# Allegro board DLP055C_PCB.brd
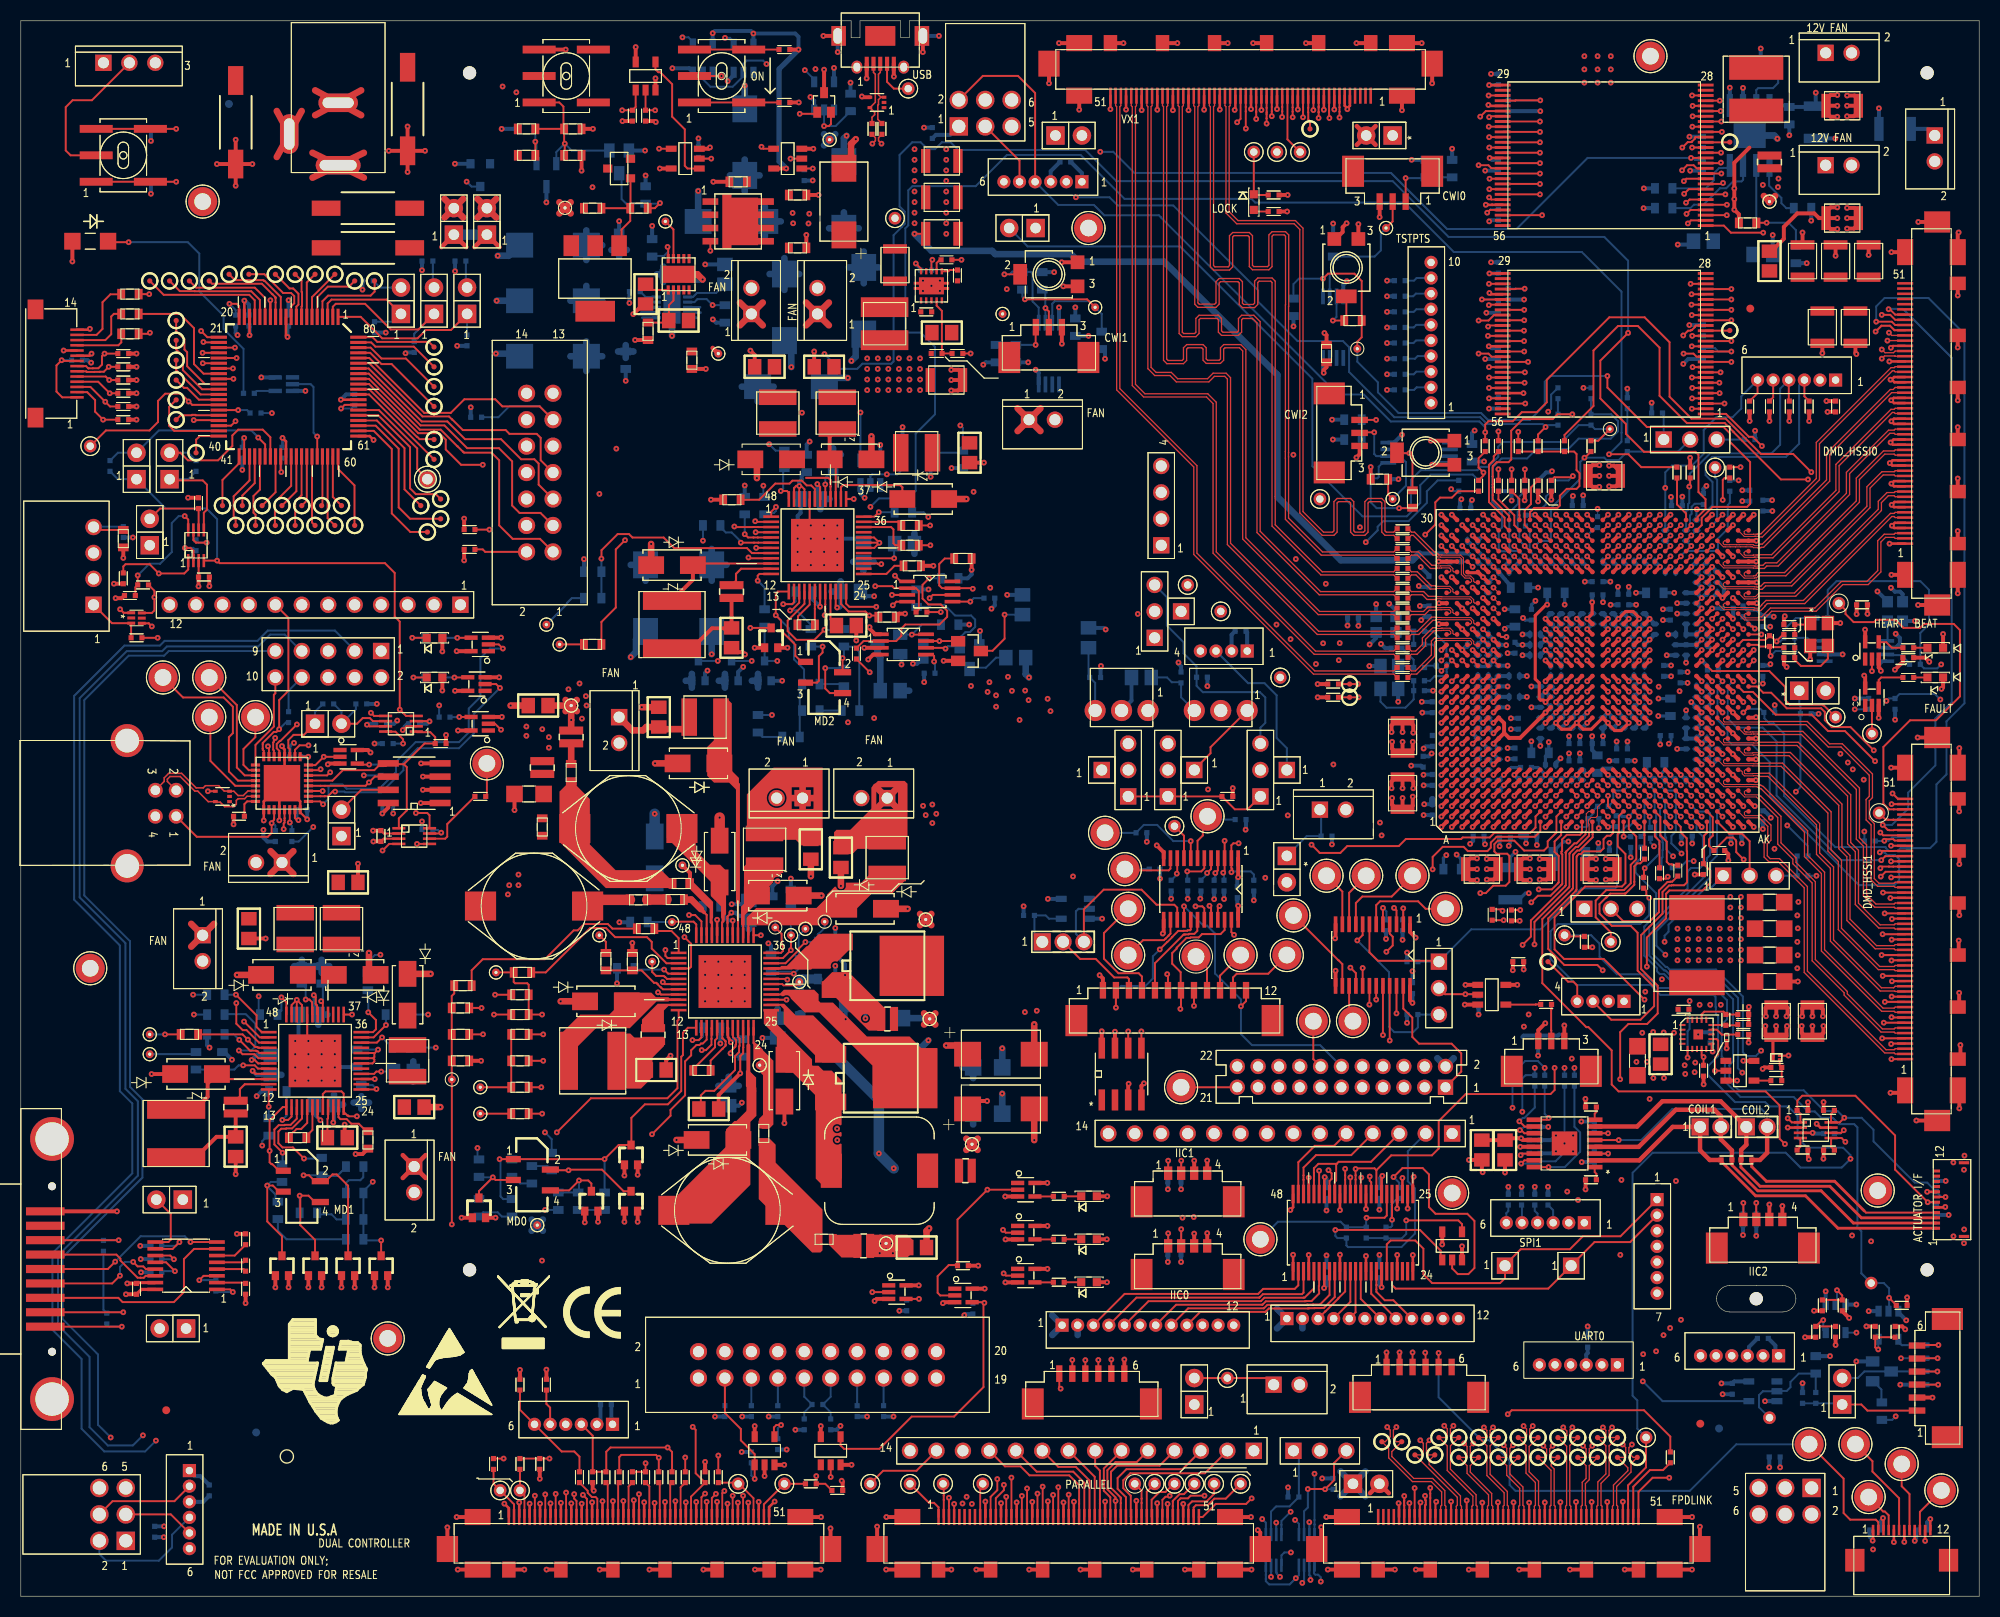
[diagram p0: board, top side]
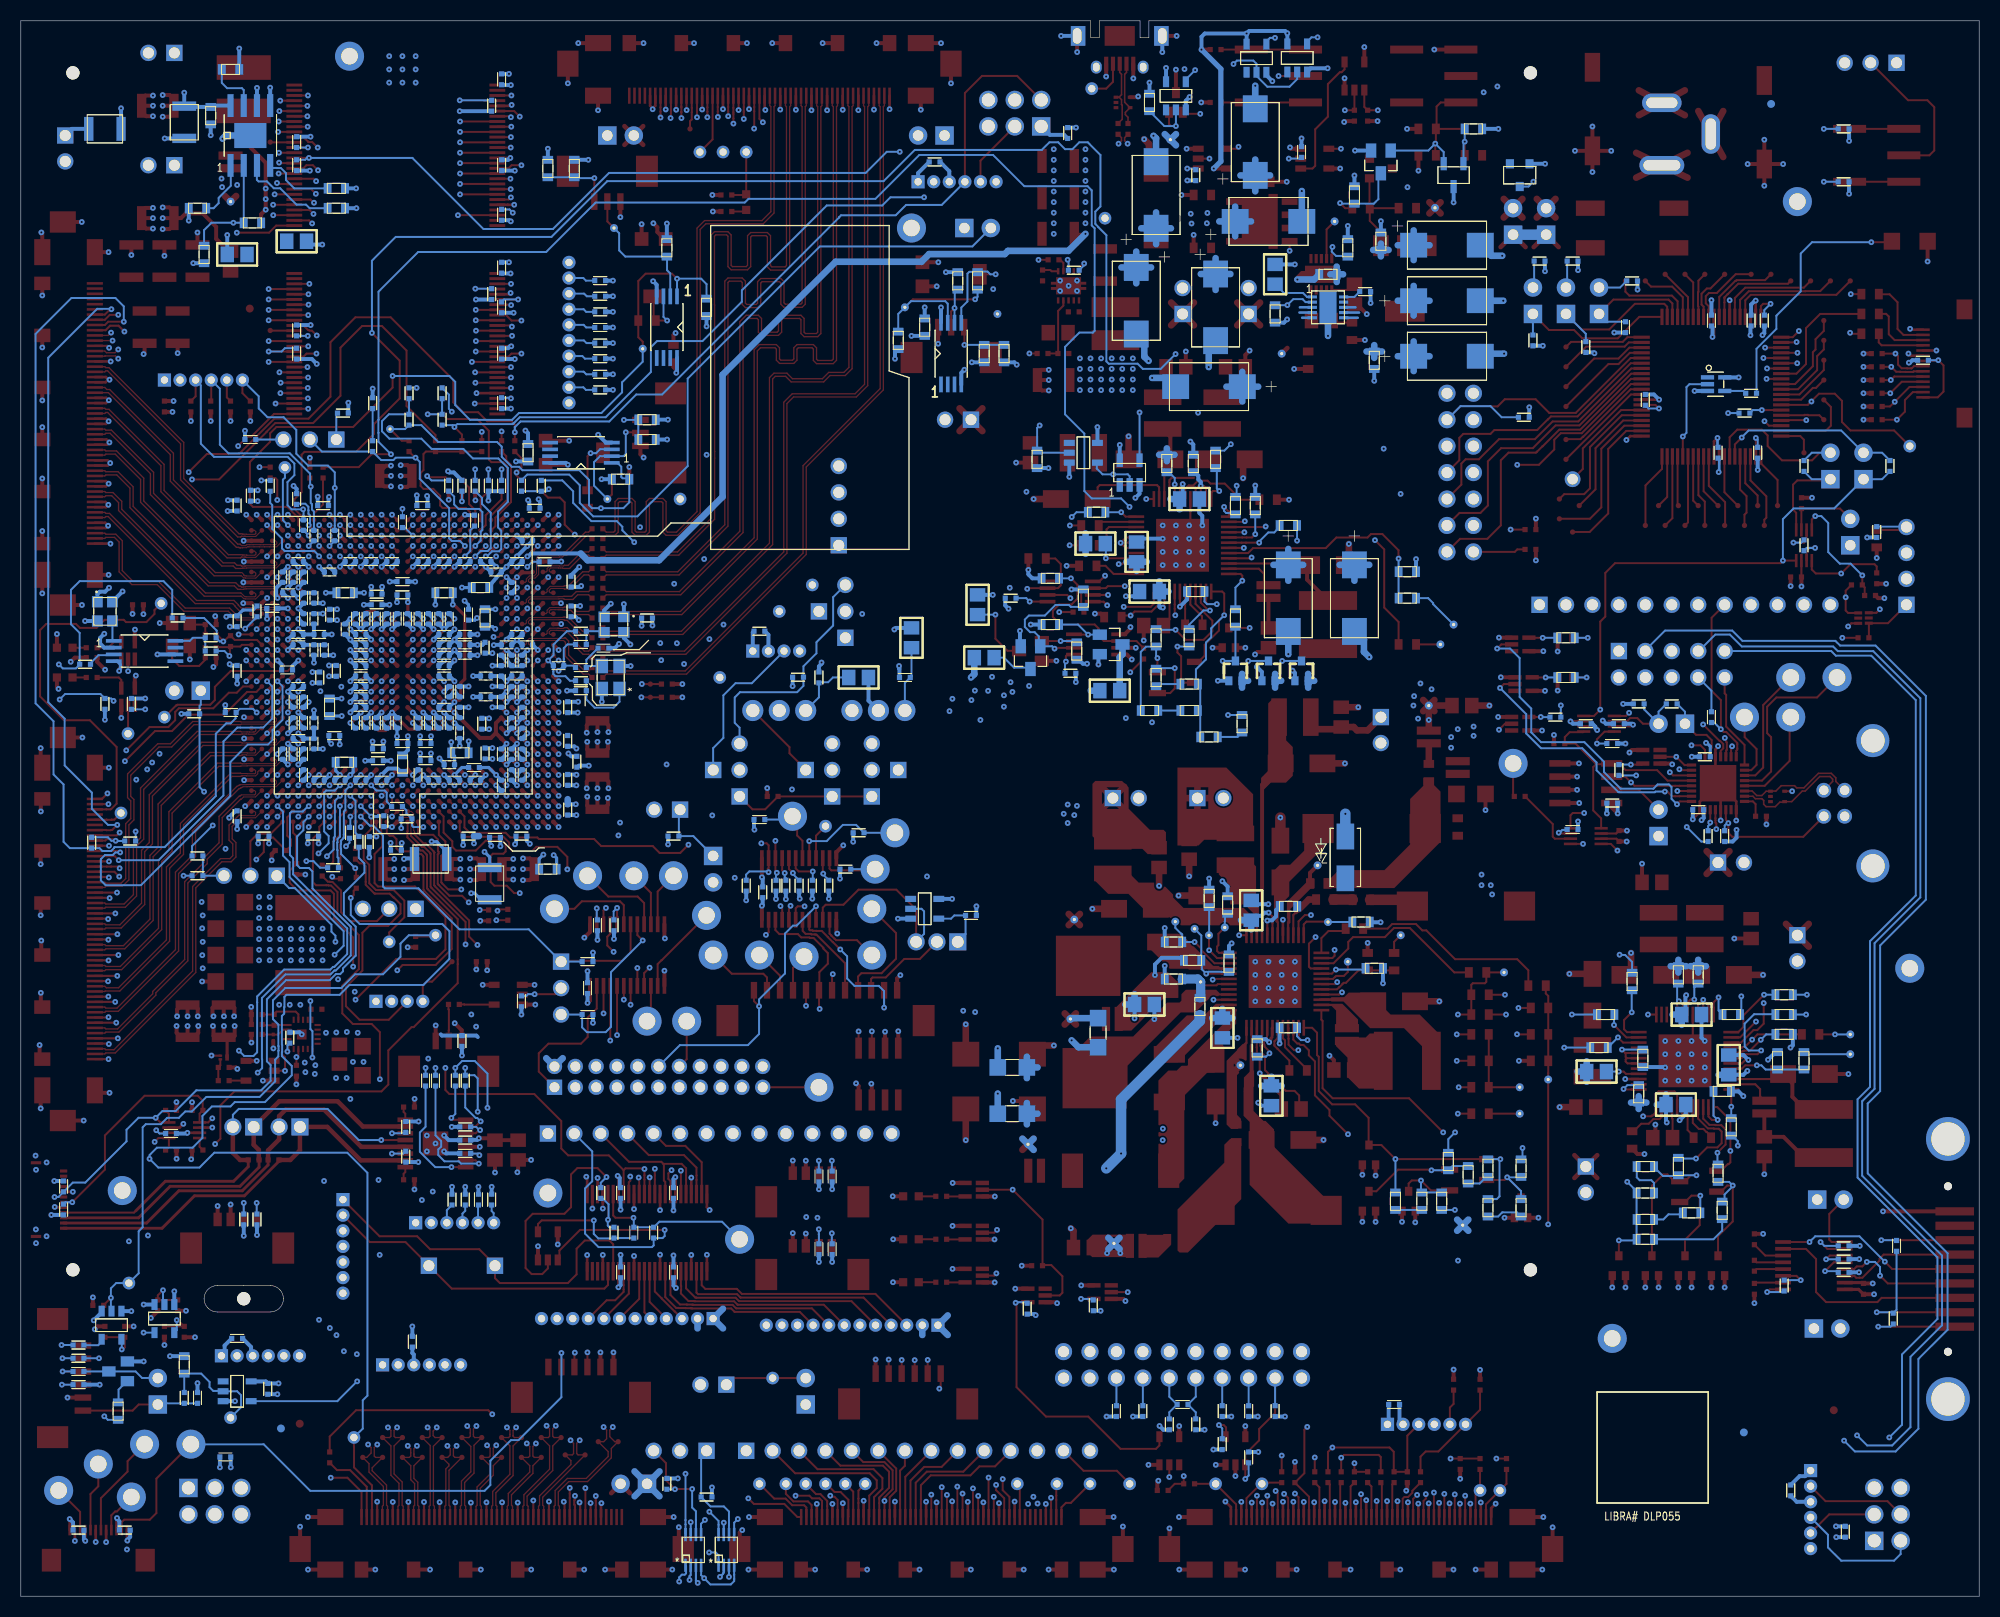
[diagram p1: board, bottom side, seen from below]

Outline 188.1 x 151.35 mm; copper layers: TOP, L2_GND, LY3, LY4_GND, LY5, LY6_GND, LY7_PLANE, LY8_PLANE, LY9_GND, LY10, LY11_GND, LY12, L13_GND, BOTTOM. Coordinates in mm from the lower left corner of the outline.
Outline path: 0,151.35 0,0 188.1,0 188.1,151.35 85.35,151.35 85.35,149.75 84.5,149.75 84.5,151.35 80.6,151.35 80.6,149.75 79.75,149.75 79.75,151.35 0,151.35

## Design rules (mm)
net group DIFFPAIR24: nets DMD_LS0_WDATA_N DMD_LS0_WDATA_P
net group DIFFPAIR37: nets USBDM USBDP
net group GROUP1: nets DMD_LS0_CLK_N DMD_LS0_CLK_P
net group USB_DAT_N: nets USB_DAT_N USB_DAT_N_IN
net group USB_DAT_P: nets USB_DAT_P USB_DAT_P_IN
net group DMD_HSSI0: nets DMD_HSSI0_CLK_N DMD_HSSI0_CLK_P DMD_HSSI0_N_0 DMD_HSSI0_N_1 DMD_HSSI0_N_2 DMD_HSSI0_N_3 DMD_HSSI0_N_4 DMD_HSSI0_N_5 DMD_HSSI0_N_6 DMD_HSSI0_N_7 DMD_HSSI0_P_0 DMD_HSSI0_P_1 DMD_HSSI0_P_2 DMD_HSSI0_P_3 DMD_HSSI0_P_4 DMD_HSSI0_P_5 DMD_HSSI0_P_6 DMD_HSSI0_P_7
net group DMD_HSSI1: nets DMD_HSSI1_CLK_N DMD_HSSI1_CLK_P DMD_HSSI1_N_0 DMD_HSSI1_N_1 DMD_HSSI1_N_2 DMD_HSSI1_N_3 DMD_HSSI1_N_4 DMD_HSSI1_N_5 DMD_HSSI1_N_6 DMD_HSSI1_N_7 DMD_HSSI1_P_0 DMD_HSSI1_P_1 DMD_HSSI1_P_2 DMD_HSSI1_P_3 DMD_HSSI1_P_4 DMD_HSSI1_P_5 DMD_HSSI1_P_6 DMD_HSSI1_P_7
net group FP-100DIFF: nets FP_A_A_N FP_A_A_P FP_A_B_N FP_A_B_P FP_A_C_N FP_A_C_P FP_A_CLK_N FP_A_CLK_P FP_A_D_N FP_A_D_P FP_A_E_N FP_A_E_P FP_B_A_N FP_B_A_P FP_B_B_N FP_B_B_P FP_B_C_N FP_B_C_P FP_B_CLK_N FP_B_CLK_P FP_B_D_N FP_B_D_P FP_B_E_N FP_B_E_P

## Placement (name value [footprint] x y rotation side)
ASY1  -  [#2]  31.42 14.33 180 bottom
C1  10uF  [1210]  174.94 143.19 0 top
C2  100uF  [1210]  88.46 137.89 180 top
C5  22uF  [1210]  83.96 127.89 90 top
C6  100uF  [1210]  88.46 134.39 180 top
C7  22uF  [1210]  88.46 130.89 180 top
C8  10uF  [1210]  174.94 132.4 0 top
C10  100pF  [0603]  172.4 22.23 90 bottom
C14  100nF  [0402]  86.96 123.39 180 top
C15  2.2uF  [0805]  88.46 121.39 180 top
C18  22 uF  [0805]  78.77 70.96 90 top
C27  22uF  [1210]  88.9 116.84 180 top
C34  100uF  [1210]  152.08 107.63 0 top
C49  100nF  [0402]  132.72 102.55 180 top
C50  100nF  [0402]  132.72 101.6 180 top
C51  100nF  [0402]  132.72 100.65 180 top
C52  100nF  [0402]  132.72 99.7 180 top
C53  100nF  [0402]  132.72 98.74 180 top
C54  100nF  [0402]  132.72 97.79 180 top
C58  100uF  [7343]  69.53 139.7 90 bottom
C59  100uF  [7343]  79.06 133.98 90 top
C60  0.1 uF  [0603]  64.45 118.75 270 top
C61  100nF  [0402]  132.72 96.84 180 top
C62  100nF  [0402]  132.72 95.89 180 top
C63  100nF  [0402]  132.72 94.93 180 top
C64  100nF  [0402]  132.72 93.98 180 top
C65  100nF  [0402]  132.72 93.03 180 top
C66  100nF  [0402]  132.72 92.08 180 top
C67  100nF  [0402]  132.72 91.12 180 top
C68  100nF  [0402]  132.72 90.17 180 top
C69  15pF  [0402]  169.86 93.34 0 top
C70  15pF  [0402]  169.86 90.17 0 top
C71  10uF  [1210]  180.02 140.97 180 bottom
C72  100nF  [0402]  132.72 89.22 180 top
C73  100nF  [0402]  132.72 88.27 180 top
C74  100uF  [1210]  132.72 82.55 90 top
C91  100uF  [1210]  132.72 77.15 270 top
C95  100uF  [1210]  140.34 69.85 0 top
C96  100uF  [1210]  145.41 69.85 180 top
C97  100uF  [1210]  151.76 69.85 180 top
C108  47uF  [1206]  167.98 66.67 0 top
C109  47uF  [1206]  167.98 64.14 0 top
C110  47uF  [1206]  167.98 61.59 0 top
C124  0.1uF  [0805]  157.5 52.07 270 top
C125  100nF  [0402]  159.7 56.39 0 top
C126  1uF  [0402]  165.44 55.88 0 top
C127  47uF  [1206]  167.98 59.05 0 top
C130  47uF  [1206]  155.28 51.44 270 top
C133  10uF  [0805]  142.56 42.86 270 top
C134  22nF  [0402]  163.83 41.91 0 top
C135  22nF  [0402]  165.73 41.91 0 top
C136  0.1uF  [0402]  141.92 145.73 90 bottom
C137  0.1uF  [0402]  141.92 137.48 270 bottom
C138  100nF  [0402]  65.09 138.75 270 bottom
C141  0.1uF  [0402]  141.92 127.64 90 bottom
C147  0.1uF  [0402]  141.92 119.38 270 bottom
C148  4.7uF  [0402]  167.32 104.78 90 bottom
C149  4.7uF  [0402]  166.05 105.73 90 bottom
C150  4.7uF  [0402]  159.07 104.78 180 bottom
C151  100nF  [0402]  149.54 104.78 180 bottom
C152  10nF  [0402]  139.45 101.4 180 bottom
C153  100nF  [0402]  138.75 104.52 180 bottom
C154  100nF  [0402]  162.95 97.9 270 bottom
C155  100nF  [0402]  162.45 96.4 0 bottom
C156  100nF  [0402]  161.95 97.9 90 bottom
C157  100nF  [0402]  161.45 99.4 0 bottom
C158  100nF  [0402]  160.95 97.9 270 bottom
C159  100nF  [0402]  160.95 95.9 270 bottom
C160  10nF  [0402]  158.45 98.4 0 bottom
C161  10uF  [0603]  156.95 96.4 180 bottom
C162  10nF  [0402]  156.45 99.4 0 bottom
C163  10nF  [0402]  154.45 99.4 0 bottom
C164  1uF  [0402]  153.92 96.27 180 bottom
C165  100nF  [0402]  152.45 99.4 0 bottom
C166  100nF  [0402]  151.45 97.47 180 bottom
C167  1uF  [0402]  151.45 96.2 0 bottom
C168  10nF  [0402]  149.45 99.4 0 bottom
C169  10nF  [0402]  147.45 99.4 0 bottom
C170  10uF  [0603]  147.45 96.4 0 bottom
C171  10nF  [0402]  145.45 99.4 0 bottom
C172  10uF  [0603]  143.95 96.9 0 bottom
C173  10nF  [0402]  143.45 99.4 180 bottom
C174  100nF  [0402]  140.95 96.9 270 bottom
C175  100nF  [0402]  140.45 99.4 0 bottom
C176  4.7uF  [0402]  135.25 97.47 270 bottom
C177  100nF  [0402]  167.32 93.66 270 bottom
C178  100nF  [0402]  163.95 94.9 0 bottom
C179  100nF  [0402]  161.45 92.4 0 bottom
C180  100nF  [0402]  161.45 91.4 0 bottom
C181  100nF  [0402]  160.95 93.9 90 bottom
C182  100nF  [0402]  159.95 90.9 270 bottom
C183  100nF  [0402]  159.45 92.4 180 bottom
C184  4.7uF  [0402]  158.43 94.3 270 bottom
C185  100nF  [0402]  155.95 93.9 270 bottom
C186  470nF  [0402]  155.45 92.4 180 bottom
C187  100nF  [0402]  155.45 91.4 180 bottom
C188  100nF  [0402]  154.95 93.9 270 bottom
C189  100nF  [0402]  153.95 93.9 270 bottom
C190  1uF  [0402]  153.92 95.25 0 bottom
C191  100nF  [0402]  152.95 93.9 270 bottom
C192  100nF  [0402]  151.95 93.9 270 bottom
C193  100nF  [0402]  150.95 93.9 270 bottom
C194  100nF  [0402]  149.95 93.9 270 bottom
C195  100nF  [0402]  148.95 93.9 270 bottom
C196  100nF  [0402]  147.95 93.9 270 bottom
C197  22nF  [0402]  147.45 92.4 0 bottom
C198  22nF  [0402]  147.45 91.4 0 bottom
C199  470nF  [0402]  146.95 93.9 270 bottom
C200  220nF  [0402]  145.45 92.4 180 bottom
C201  4.7uF  [0402]  145.1 94.3 90 bottom
C202  10uF  [0603]  143.51 93.98 90 bottom
C203  4.7uF  [0402]  143.51 91.12 270 bottom
C204  100nF  [0402]  140.45 92.4 0 bottom
C205  220nF  [0402]  139.45 91.4 180 bottom
C206  100nF  [0402]  135.25 94.61 270 bottom
C207  4.7uF  [0402]  167.32 88.9 270 bottom
C208  100nF  [0402]  162.52 88.99 0 bottom
C209  100nF  [0402]  161.95 85.9 90 bottom
C210  100nF  [0402]  161.45 87.4 180 bottom
C211  100nF  [0402]  160.95 85.9 90 bottom
C212  4.7uF  [0402]  159.38 88.27 90 bottom
C213  1uF  [0402]  157.8 88.9 270 bottom
C214  100nF  [0402]  155.45 90.4 180 bottom
C215  100nF  [0402]  155.45 89.4 180 bottom
C216  100nF  [0402]  155.45 88.4 0 bottom
C217  100nF  [0402]  155.45 87.4 180 bottom
C218  100nF  [0402]  155.45 86.4 180 bottom
C219  100nF  [0402]  147.45 90.4 0 bottom
C220  100nF  [0402]  147.45 89.4 0 bottom
C221  100nF  [0402]  147.45 88.4 0 bottom
C222  100nF  [0402]  146.95 86.9 90 bottom
C223  1uF  [0402]  145.95 86.9 90 bottom
C224  100nF  [0402]  143.45 88.4 0 bottom
C225  100nF  [0402]  143.45 86.4 0 bottom
C226  100nF  [0402]  140.95 89.9 90 bottom
C227  100nF  [0402]  140.95 86.9 270 bottom
C228  100nF  [0402]  140.45 88.4 180 bottom
C229  100nF  [0402]  139.95 89.9 90 bottom
C230  100nF  [0402]  139.95 86.9 270 bottom
C231  15pF  [0402]  132.14 91.08 0 bottom
C232  15pF  [0402]  134.3 87 180 bottom
C233  100nF  [0402]  162.95 80.9 90 bottom
C234  100nF  [0402]  161.95 83.9 270 bottom
C235  100nF  [0402]  161.95 80.9 270 bottom
C236  100nF  [0402]  161.45 82.4 0 bottom
C237  10nF  [0402]  160.95 83.9 270 bottom
C238  100nF  [0402]  160.95 80.9 270 bottom
C239  100nF  [0402]  159.95 81.9 270 bottom
C240  10uF  [0603]  158.45 85.4 270 bottom
C241  1uF  [0402]  157.99 82.68 0 bottom
C242  10uF  [0603]  157.02 80.12 0 bottom
C243  470nF  [0402]  155.95 83.9 90 bottom
C244  100nF  [0402]  155.45 85.4 180 bottom
C245  100nF  [0402]  154.95 83.9 90 bottom
C246  100nF  [0402]  153.95 83.9 90 bottom
C247  1uF  [0402]  153.8 81.41 0 bottom
C248  100nF  [0402]  152.95 83.9 90 bottom
C249  100nF  [0402]  151.95 83.9 90 bottom
C250  1uF  [0402]  151.45 81.92 180 bottom
C251  100nF  [0402]  149.95 83.9 90 bottom
C252  1uF  [0402]  149.22 81.92 0 bottom
C253  470nF  [0402]  148.95 83.9 90 bottom
C254  100nF  [0402]  147.95 83.9 90 bottom
C255  1uF  [0402]  147.45 85.4 0 bottom
C256  100nF  [0402]  146.95 83.9 90 bottom
C257  1uF  [0402]  145.95 84.9 90 bottom
C258  1uF  [0402]  145.95 82.9 270 bottom
C259  10uF  [0603]  145.92 81.03 180 bottom
C260  1uF  [0402]  143.83 83.82 270 bottom
C261  4.7uF  [0402]  143.51 80.96 270 bottom
C262  1uF  [0402]  141.95 80.9 270 bottom
C263  100nF  [0402]  140.95 83.9 270 bottom
C264  220nF  [0402]  140.95 80.9 90 bottom
C265  1uF  [0402]  139.95 84.9 270 bottom
C266  220nF  [0402]  139.95 82.9 270 bottom
C267  1uF  [0402]  139.95 80.9 90 bottom
C268  100nF  [0402]  135.57 85.41 270 bottom
C269  4.7uF  [0402]  135.57 82.17 270 bottom
C275  100nF  [0402]  160.95 78.9 270 bottom
C276  10nF  [0402]  159.45 78.4 180 bottom
C277  10nF  [0402]  157.45 78.4 180 bottom
C278  10nF  [0402]  155.45 78.4 180 bottom
C279  1uF  [0402]  153.8 80.26 0 bottom
C280  10nF  [0402]  153.45 78.4 180 bottom
C281  100nF  [0402]  149.95 78.9 270 bottom
C282  1uF  [0402]  149.22 80.26 0 bottom
C283  10nF  [0402]  148.45 78.4 0 bottom
C284  1uF  [0402]  146.94 79.88 0 bottom
C285  10nF  [0402]  146.45 78.4 0 bottom
C286  22nF  [0402]  144.45 78.4 180 bottom
C287  22nF  [0402]  141.95 77.9 270 bottom
C288  1uF  [0402]  140.95 78.9 270 bottom
C289  1uF  [0402]  139.95 78.9 270 bottom
C290  4.7uF  [0402]  135.57 78.42 270 bottom
C291  4.7uF  [0402]  135.57 75.56 270 bottom
C298  100nF  [0402]  167.32 74.93 270 bottom
C299  100nF  [0402]  164.78 73.03 180 bottom
C300  4.7uF  [0402]  160.02 73.03 180 bottom
C301  4.7uF  [0402]  134.69 80.17 90 bottom
C302  4.7uF  [0402]  152.07 71.66 0 bottom
C303  1uF  [0402]  145.1 73.03 0 bottom
C304  4.7uF  [0402]  140.02 73.03 180 bottom
C317  15nF  [0402]  162.26 53.66 90 bottom
C320  100nF  [0402]  145.41 43.81 0 bottom
C321  100nF  [0402]  150.5 24.45 270 bottom
C502  100nF  [0402]  133.67 58.42 270 bottom
C503  100nF  [0402]  180.02 25.4 270 top
C504  100nF  [0402]  174.31 25.4 90 top
C507  100nF  [0402]  178.12 6.35 180 bottom
C508  100nF  [0402]  182.56 6.35 0 bottom
C511  100nF  [0402]  9.84 102.23 270 bottom
C514  100nF  [0402]  17.59 97.92 0 top
C515  100nF  [0402]  16.83 100.97 270 bottom
C517  100nF  [0402]  127.95 93.98 180 bottom
C519  100nF  [0402]  25.08 109.86 270 bottom
C520  100nF  [0402]  25.72 122.56 270 bottom
C521  470nF  [0402]  20.64 122.56 270 bottom
C528  100nF  [0402]  35.24 76.2 180 bottom
C529  100nF  [0402]  39.05 73.66 180 bottom
C530  100nF  [0402]  34.59 73.03 270 top
C531  220nF  [0402]  32.07 114.94 270 bottom
C547  100nF  [0402]  37.78 83.82 180 bottom
C548  100nF  [0402]  34.61 83.82 180 bottom
C549  100nF  [0402]  21.91 122.56 90 bottom
C557  10uF  [0603]  151.43 79.94 90 bottom
C576  10uF  [0603]  137.48 69.85 180 bottom
C583  100uF  [1210]  143.07 68.45 270 bottom
C585  220nF  [0402]  21.27 109.86 270 bottom
C622  100nF  [0402]  26.99 75.56 0 bottom
C623  100nF  [0402]  26.35 80.64 180 bottom
C624  1uF  [0402]  20.95 74.93 180 top
C625  100nF  [0402]  24.45 73.03 270 bottom
C654  100nF  [0402]  164.38 19.92 90 bottom
C664  100nF  [0402]  143.83 60.96 0 top
C665  100nF  [0402]  11.11 29.53 90 top
C666  100nF  [0402]  125.41 31.11 270 bottom
C667  100nF  [0402]  130.49 31.11 270 bottom
C668  22uF  [1210]  177.48 128.27 90 top
C669  22uF  [1210]  171.13 128.27 90 top
C670  100nF  [0402]  176.85 95.25 0 top
C675  100nF  [0402]  116.84 67.63 270 bottom
C676  100nF  [0402]  56.2 18.41 0 bottom
C677  22uF  [1210]  173.04 121.92 270 top
C678  22uF  [1210]  176.21 121.92 270 top
C679  22uF  [1210]  174.31 128.27 90 top
C682  100nF  [0402]  125.41 38.73 90 bottom
C683  100nF  [0402]  130.49 38.73 90 bottom
C684  100nF  [0402]  181.29 90.17 180 top
C687  100nF  [0402]  100.33 137.79 180 bottom
C688  100nF  [0402]  87.55 140.57 270 bottom
C689  100nF  [0402]  168.46 13.38 0 bottom
C690  100nF  [0402]  167.32 24.77 180 bottom
C691  100nF  [0402]  18.73 29.84 270 bottom
C692  100nF  [0402]  21.59 29.53 270 top
C693  100nF  [0402]  21.59 31.75 270 top
C694  100nF  [0402]  21.59 34.29 90 top
C695  100nF  [0402]  18.1 10.16 270 bottom
C696  100nF  [0402]  12.86 6.19 270 bottom
C697  4.7uF  [0805]  107.63 88.27 0 bottom
C698  4.7uF  [0805]  102.55 92.08 270 bottom
C699  100uF  [1210]  148.74 70.82 0 bottom
C700  100nF  [0402]  174.31 114.3 90 top
C752  0.33 uF  [0805]  66.08 46.8 0 top
C753  0.33 uF  [0805]  69.92 65.9 270 bottom
C754  0.33 uF  [0805]  72.69 54.59 90 bottom
C755  0.33 uF  [0805]  67.98 48.07 90 bottom
C756  0.22 uF  [0603]  65.42 50.51 0 top
C757  0.22 uF  [0603]  69.35 52.67 270 bottom
C758  47 uF  [1206]  92.87 46.35 0 bottom
C759  47 uF  [1206]  92.87 50.8 0 bottom
C760  100uF  [7343]  94.14 46.81 0 top
C761  100uF  [7343]  94.14 52.07 0 top
C762  47 uF  [1206]  84.63 54.14 270 bottom
C763  47 uF  [1206]  48.81 77.07 180 top
C764  22 uF  [0805]  86.04 33.49 180 top
C765  22 uF  [0805]  49.69 85.56 0 top
C766  22 uF  [0805]  61.03 50.55 180 top
C767  0.001 uF  [0603]  47.18 41.12 90 bottom
C768  0.001 uF  [0603]  47.18 37.31 90 bottom
C769  0.001 uF  [0603]  56.07 37.95 90 bottom
C770  22 uF  [0805]  75.88 71.75 90 top
C771  22 uF  [0805]  61.28 84.45 270 top
C772  0.1 uF  [0603]  58.74 60.96 90 top
C773  0.33 uF  [0805]  30.4 44.05 0 top
C774  0.33 uF  [0805]  27.62 55.88 0 bottom
C775  0.33 uF  [0805]  24.05 51.04 270 bottom
C776  0.33 uF  [0805]  29.13 47.23 0 bottom
C777  0.22 uF  [0603]  26.59 44.05 0 top
C778  0.22 uF  [0603]  32.3 51.67 90 bottom
C779  22 uF  [0805]  20.64 43.18 90 top
C780  0.001 uF  [0603]  32.07 38.73 0 bottom
C781  0.001 uF  [0603]  32.07 34.29 0 bottom
C782  0.001 uF  [0603]  32.07 36.2 0 bottom
C783  22 uF  [0805]  37.78 46.99 180 top
C784  22 uF  [0805]  31.43 68.58 180 top
C785  22 uF  [0805]  21.91 64.14 90 top
C786  0.1 uF  [0603]  19.37 51.44 90 bottom
C787  0.33 uF  [0805]  79.29 93.25 0 top
C788  0.33 uF  [0805]  79.69 96.52 180 bottom
C789  0.33 uF  [0805]  75.85 105.41 0 bottom
C790  0.33 uF  [0805]  80.93 100.33 270 bottom
C791  0.22 uF  [0603]  75.43 93.33 0 top
C792  0.22 uF  [0603]  75.48 108.82 270 bottom
C793  22 uF  [0805]  68.26 92.08 90 top
C794  0.001 uF  [0603]  75.88 85.09 180 bottom
C795  0.001 uF  [0603]  73.98 82.55 0 bottom
C796  0.001 uF  [0603]  75.88 87.63 180 bottom
C797  22 uF  [0805]  91.12 109.86 90 top
C798  22 uF  [0805]  77.15 118.11 0 top
C799  22 uF  [0805]  71.44 118.11 0 top
C800  0.1 uF  [0603]  54.93 98.42 180 bottom
C801  22 uF  [0805]  60.01 125.09 270 top
C802  100uF  [7343]  73.34 123.83 270 bottom
C803  100uF  [7343]  68.26 132.08 180 bottom
C804  100uF  [7343]  80.96 124.46 270 bottom
C805  100uF  [7343]  79.06 134.62 90 bottom
C806  0.1 uF  [0603]  74.61 134.62 0 top
C807  0.1 uF  [0603]  68.9 135.89 180 top
C808  0.1 uF  [0603]  74.61 129.54 0 top
C809  0.1 uF  [0603]  53.02 138.43 0 top
C810  10 uF  [1210]  172.4 141.6 90 bottom
C811  0.1 uF  [0603]  169.86 142.24 270 bottom
C812  0.1 uF  [0603]  167.96 146.69 180 bottom
C813  10 pF  [0603]  165.86 131.94 0 top
C814  22 uF  [0805]  161.61 130.17 0 bottom
C815  22 uF  [0805]  167.32 128.91 180 bottom
C816  1 uF  [0603]  157.8 133.35 180 bottom
C817  0.1 uF  [0603]  157.8 135.25 180 bottom
C818  0.047 uF  [0402]  93.03 95.89 180 bottom
C819  0.01 uF  [0402]  87.29 88.67 0 bottom
C820  22 uF  [0805]  67.63 127 90 bottom
C821  100uF  [7343]  51.12 119.13 180 bottom
C822  100uF  [7343]  51.12 129.79 180 bottom
C823  100uF  [7343]  60.01 95.89 270 bottom
C824  100uF  [7343]  51.12 124.46 180 bottom
C825  100uF  [7343]  73.98 116.2 0 bottom
C826  100uF  [7343]  66.36 95.89 270 bottom
C827  0.1 uF  [0603]  62.55 127 0 bottom
C828  0.1 uF  [0603]  57.47 130.17 90 bottom
C829  0.1 uF  [0603]  58.1 118.75 270 bottom
C830  100nF  [0402]  145.73 53.34 90 bottom
C831  0.1 uF  [0603]  125.41 119.38 90 top
C832  0.1 uF  [0603]  134.94 137.16 90 bottom
C833  0.1 uF  [0603]  101.28 121.92 270 bottom
C834  0.1 uF  [0603]  95.57 119.38 270 bottom
C835  0.1 uF  [0603]  139.38 109.86 90 bottom
C836  0.1 uF  [0603]  127.95 113.03 180 bottom
C837  100nF  [0402]  117.16 92.71 180 bottom
D1  Green  [LED-LTST-C190_LITEON]  118.43 133.98 270 top
D5  Green  [LED-LTST-C190_LITEON]  102.55 38.42 0 top
D6  Red  [LED-LTST-C190_LITEON]  183.83 88.27 0 top
D7  Green  [LED-LTST-C190_LITEON]  102.55 34.29 0 top
D8  Red  [LED-LTST-C190_LITEON]  102.55 30.16 0 top
D10  Red  [LED-LTST-C190_LITEON]  39.69 92.08 0 top
D15  Green  [LED-LTST-C190_LITEON]  183.83 91.12 0 top
D30  B220A-13-F  [DIO-SMA_DIO-MOD]  73.34 49.53 90 top
D32  B220A-13-F  [DIO-SMA_DIO-MOD]  60.88 70.98 270 bottom
D35  B220A-13-F  [DIO-SMA_DIO-MOD]  66.92 43.83 0 top
D36  B220A-13-F  [DIO-SMA_DIO-MOD]  67.12 70.58 270 top
D37  B220A-13-F  [DIO-SMA_DIO-MOD]  56.2 57.15 0 top
D38  B220A-13-F  [DIO-SMA_DIO-MOD]  81.09 66.04 180 top
D39  B220A-13-F  [DIO-SMA_DIO-MOD]  72.71 67.31 180 top
D40  B220A-13-F  [DIO-SMA_DIO-MOD]  65.09 80.01 0 top
D41  B220A-13-F  [DIO-SMA_DIO-MOD]  16.83 50.16 0 top
D42  B220A-13-F  [DIO-SMA_DIO-MOD]  37.15 57.78 270 top
D43  B220A-13-F  [DIO-SMA_DIO-MOD]  32.07 59.69 180 top
D44  B220A-13-F  [DIO-SMA_DIO-MOD]  25.08 59.69 0 top
D45  B220A-13-F  [DIO-SMA_DIO-MOD]  62.55 99.06 0 top
D46  B220A-13-F  [DIO-SMA_DIO-MOD]  86.68 105.41 180 top
D47  B220A-13-F  [DIO-SMA_DIO-MOD]  79.69 109.22 180 top
D48  B220A-13-F  [DIO-SMA_DIO-MOD]  72.07 109.22 0 top
D49  BZX84C8V2LT1G  [SOT-23_ON-SEMI]  57.47 137.16 270 top
D50  LMV431  [SOIC3-DBZ_TI]  50.48 136.53 180 bottom
D51  BZX84C8V2LT1G  [SOT-23_ON-SEMI]  44.13 136.53 180 bottom
D52  green  [LED-1206]  6.67 130.17 180 top
D53  Green  [LED-LTST-C190_LITEON]  39.69 88.27 0 top
DN1  BAT54SWT1G  [SOT-323_SC70_ONSEMI_MOD]  54.8 37.95 0 top
DN2  BAT54SWT1G  [SOT-323_SC70_ONSEMI_MOD]  58.61 37.95 0 top
DN3  BAT54SWT1G  [SOT-323_SC70_ONSEMI_MOD]  44.01 37.31 0 top
DN4  BAT54SWT1G  [SOT-323_SC70_ONSEMI_MOD]  58.61 42.39 0 top
DN5  BAT54SWT1G  [SOT-323_SC70_ONSEMI_MOD]  28.26 31.75 0 top
DN6  BAT54SWT1G  [SOT-323_SC70_ONSEMI_MOD]  31.43 31.75 0 top
DN7  BAT54SWT1G  [SOT-323_SC70_ONSEMI_MOD]  25.08 31.75 0 top
DN8  BAT54SWT1G  [SOT-323_SC70_ONSEMI_MOD]  34.61 31.75 0 top
DN9  BAT54SWT1G  [SOT-323_SC70_ONSEMI_MOD]  71.44 88.9 180 bottom
DN10  BAT54SWT1G  [SOT-323_SC70_ONSEMI_MOD]  68.26 88.9 180 bottom
DN11  BAT54SWT1G  [SOT-323_SC70_ONSEMI_MOD]  72.07 92.08 0 top
DN12  BAT54SWT1G  [SOT-323_SC70_ONSEMI_MOD]  65.09 88.9 180 bottom
F1  MMZ1608S121A  [0603]  9.84 101.6 90 top
FB1  FB  [35F0121-1SR-10_LAIRD]  33.34 133.35 0 top
FB2  FB  [35F0121-1SR-10_LAIRD]  33.34 129.54 0 top
FB3  FB  [35F0121-1SR-10_LAIRD]  37.15 142.88 90 top
FB4  FB  [35F0121-1SR-10_LAIRD]  20.64 141.6 90 top
FID  -  [unnamed#3]  161.31 16.57 0 top
FID#2  -  [unnamed#3]  166.11 123.71 0 top
FID#3  -  [unnamed#3]  13.97 17.87 0 top
FID#4  -  [unnamed#3]  19.99 143.37 180 bottom
FID#5  -  [unnamed#3]  163.11 16.11 180 bottom
FID#6  -  [unnamed#3]  22.6 15.73 180 bottom
J2  USB,TYPE AB,MICRO,TOP MNT  [MOLEX_0475901001]  82.55 149.9 270 top
J3  FI-RE51S-VF-R1300  [FI-R51-HF_VF_DUAL]  117.16 146.69 180 top
J4  B2B-EH  [JST_B2B-EH]  173.35 148.27 0 top
J5  B2B-EH  [JST_B2B-EH]  173.35 137.48 0 top
J6  B10B-ZR  [JST_B10B-ZR]  135.45 121.39 0 top
J7  FI-RE51S-HF-R1500  [FI-R51-HF_VF_DUAL]  183.51 113.63 90 top
J8  B2B-EH  [JST_B2B-EH]  183.83 140.34 270 top
J9  HDR,2P,1R  [HDR2P_1R]  170.81 87 270 top
J10  FI-RE51S-HF-R1500  [FI-R51-HF_VF_DUAL]  183.51 64.1 90 top
J11  B2B-EH  [JST_B2B-EH]  124.78 75.56 0 top
J12  53398-0471  [CONN4-53398_MOLEX]  112.08 40.64 0 top
J14  M22-2510205  [HDR2_2MM]  161.29 45.09 0 top
J15  M22-2510205  [HDR2_2MM]  165.73 45.09 0 top
J16  53398-0471  [CONN4-53398_MOLEX]  112.08 33.66 0 top
J17  5034801200  [MOLEX_5034801200_2GPADS]  183.99 38.1 90 top
J20  53398-0671  [CONN6-53398-0690_MOLEX]  102.87 20.32 0 top
J21  53398-0671  [CONN6-53398-0690_MOLEX]  134.3 20.95 0 top
J22  B6B-ZR  [HDR1X6-B6B-ZR_JST]  150.18 35.88 0 top
J23  B6B-ZR  [HDR1X6-B6B-ZR_JST]  153.35 22.23 0 top
J26  HDR,2P,1R  [HDR2P_1R]  174.94 18.41 0 top
J27  53398-0671  [CONN6-53398-0690_MOLEX]  183.2 20.95 90 top
J28  FH12-12S-0.5SH(55)  [CONN12-FH12_HRS]  180.66 6.35 0 top
J42  FI-RE51S-VF-R1300  [FI-R51-HF_VF_DUAL]  142.88 5.08 0 top
J43  HDR,14P,1R  [HDR1X14]  118.43 13.97 180 top
J44  FI-RE51S-VF-R1300  [FI-R51-HF_VF_DUAL]  100.65 5.08 0 top
J45  B6B-ZR  [HDR1X6-B6B-ZR_JST]  56.83 16.51 0 top
J51  S4B-EH(LF)(SN)  [CONN4-S4BEH_JST]  6.98 95.25 90 top
J52  HDR,2P,1R  [HDR2P_1R]  12.38 100.97 0 top
J53  HDR,2P,1R  [HDR2P_1R]  14.29 107.31 0 top
J54  HDR,2P,1R  [HDR2P_1R]  11.11 107.31 0 top
J55  HDR,2P,1R  [HDR2P_1R]  36.51 123.19 0 top
J56  HDR,2P,1R  [HDR2P_1R]  39.69 123.19 0 top
J57  HDR,2P,1R  [HDR2P_1R]  42.86 123.19 0 top
J60  HDR,2P,1R  [HDR2P_1R]  127.95 10.79 270 top
J61  HDR,2P,1R  [HDR2P_1R]  112.71 18.41 0 top
J62  B2B-EH  [JST_B2B-EH]  120.33 20.32 0 top
J64  HDR,3P,1R  [HDR1X3]  122.24 13.97 0 top
J67  HDR,2P,1R  [HDR2P_1R]  131.76 140.34 90 top
J68  HDR,2P,1R  [HDR2P_1R]  99.38 140.34 270 top
J69  XF2M-1415-1A  [CONN14-XF2M-REV-A_OMRON]  5.4 118.43 270 top
J70  HDR,14P,2R,SHROUDED  [HDR7X2-5103308_TYCO]  51.12 100.33 180 top
J72  HDR,2P,1R  [HDR2P_1R]  30.8 73.03 0 top
J73  B4B-ZR  [HDR1X4-B4B-ZR_JST]  117.79 90.8 0 top
J74  HDR,4P,1R  [HDR1X4]  109.54 100.97 90 top
J75  HDR,10P,2R  [HDR2X5]  34.61 90.8 180 top
J76  HDR,3P,1R  [HDR1X3]  119.06 76.83 90 top
J77  HDR,1P,1R  [HDR1]  121.6 79.38 0 top
J78  HDR,3P,1R  [HDR1X3]  108.9 92.08 90 top
J79  HDR,1P,1R  [HDR1]  111.44 94.61 0 top
J82  HDR,3P,1R  [HDR1X3]  157.8 111.12 0 top
J83  USB,Type-B  [CONN4-USB-897-43-004-90_MILL]  14.92 74.93 270 top
J84  HDR,2P,1R  [HDR2P_1R]  28.26 83.82 270 top
J85  B3B-EH  [CONN3-B3B-EH_JST]  7.94 147.32 180 top
J86  HDR,3P,1R  [HDR1X3]  136.21 60.96 270 top
J87  HDR,3P,1R  [HDR1X3]  110.17 76.83 90 top
J88  HDR,1P,1R  [HDR1]  112.71 79.38 0 top
J89  HDR,3P,1R  [HDR1X3]  106.36 76.83 90 top
J90  HDR,1P,1R  [HDR1]  103.82 79.38 0 top
J94  HDR,2P,1R  [HDR2P_1R]  15.88 25.72 90 top
J95  HDR,2P,1R  [HDR2P_1R]  15.56 38.1 90 top
J96  HDR,12P,1R  [HDR1X12]  42.23 95.25 180 top
J97  B22B-PHDSS(LF)(SN)  [CONN22-B22B-PHD_JST]  136.84 48.89 90 top
J98  HDR,2P,1R  [HDR2P_1R]  97.47 131.44 90 top
J102  RS232  [CONN9-190-009-A_NORCOMP_REV]  2.35 31.43 90 top
J103  B6B-ZR  [HDR1X6-B6B-ZR_JST]  101.92 135.89 0 top
J104  B6B-ZR  [HDR1X6-B6B-ZR_JST]  16.19 12.07 90 top
J105  B6B-ZR  [HDR1X6-B6B-ZR_JST]  168.83 23.1 0 top
J106  HDR,3P,1R  [HDR1X3_2MM]  98.11 62.86 0 top
J110  HDR,14P,1R  [HDR1X14]  137.48 44.45 180 top
J111  HDR,6P,2R,RA  [HDR-2X3-A-RA]  90.09 141.21 180 top
J112  HDR,6P,2R,RA  [HDR-2X3-A-RA]  10.08 5.32 270 top
J113  HDR,6P,2R,RA  [HDR-2X3-A-RA]  172 10.4 0 top
J114  53398-0371  [CONN3-53398-A_MOLEX]  147 53.34 0 top
J115  53398-1271  [CONN12-53398_MOLEX]  110.81 57.15 0 top
J120  B12B-ZR(LF)(SN)  [HDR1X12-B12B-ZR_JST]  100.01 26.04 180 top
J121  B12B-ZR(LF)(SN)  [HDR1X12-B12B-ZR_JST]  121.6 26.67 180 top
J122  B7B-ZR  [HDR1X7-B7B-ZR_JST]  157.16 38.1 90 top
J500  FI-RE51S-HF-R1500  [FI-R51-HF_VF_DUAL]  59.37 5.08 0 top
J501  HDR,20P,2R,SHROUDED  [HDR10X2-5103308_TYCO]  65.09 20.95 90 top
J502  HDR,3P,1R  [HDR1X3]  150.18 66.04 0 top
J503  B4B-ZR  [HDR1X4-B4B-ZR_JST]  153.99 57.15 0 top
J505  HDR,3P,1R  [HDR1X3]  163.51 69.22 0 top
J506  B6B-ZR  [HDR1X6-B6B-ZR_JST]  174.31 116.84 0 top
J515  CON4  [CONN4-52808_MOLEX]  49.09 40.49 270 top
J516  EH-2  [CONN2-B2B-EH_JST]  57.47 84.45 270 top
J517  EH-2  [CONN2-B2B-EH_JST]  75.09 76.67 180 top
J518  EH-2  [CONN2-B2B-EH_JST]  83.22 76.67 180 top
J519  CON4  [CONN4-52808_MOLEX]  26.99 39.37 270 top
J520  EH-2  [CONN2-B2B-EH_JST]  17.46 63.5 270 top
J521  EH-2  [CONN2-B2B-EH_JST]  25.08 70.48 180 top
J522  EH-2  [CONN2-B2B-EH_JST]  37.78 41.27 270 top
J523  CON4  [CONN4-52808_MOLEX]  77.15 88.27 270 top
J524  EH-2  [CONN2-B2B-EH_JST]  70.17 123.19 90 top
J525  EH-2  [CONN2-B2B-EH_JST]  76.52 123.19 90 top
J526  EH-2  [CONN2-B2B-EH_JST]  96.84 113.03 0 top
J527  HDR,2P,1R  [HDR2P_1R]  41.59 130.81 0 top
J528  HDR,2P,1R  [HDR2P_1R]  44.77 130.81 0 top
J529  PJ-002AH  [JACK-PJ-002AH_CUI]  30.48 137.48 90 top
J530  HDR,2P,1R  [HDR2P_1R]  121.6 71.12 180 top
J532  CON3  [CONN3-53398-A_MOLEX]  131.76 133.98 180 top
J533  CON3  [CONN3-53398-A_MOLEX]  98.74 121.92 0 top
J535  CON3  [CONN3-53398-A_MOLEX]  128.59 111.76 270 top
J536  53398-0471  [CONN4-53398_MOLEX]  167.32 36.2 0 top
L2  3.3uH  [COILCRAFT_LPS4018]  82.97 122.26 90 top
L11  0.68uH  [IHLP3232DZER]  160.99 62.55 90 top
L13  BLM15PX121SN1D  [0402]  159.95 95.9 270 bottom
L14  BLM15PX121SN1D  [0402]  142.45 98.4 0 bottom
L15  BLM15PX121SN1D  [0402]  159.95 93.9 90 bottom
L16  BLM15PX121SN1D  [0402]  158.95 90.9 270 bottom
L17  BLM15PX121SN1D  [0402]  156.95 92.9 90 bottom
L18  BLM15PX121SN1D  [0402]  145.45 91.4 180 bottom
L19  BLM15PX121SN1D  [0402]  141.45 91.4 0 bottom
L20  BLM15PX121SN1D  [0402]  145.45 90.4 180 bottom
L21  BLM15PX121SN1D  [0402]  141.95 89.9 270 bottom
L22  BLM15PX121SN1D  [0402]  141.95 87.9 270 bottom
L23  BLM15PX121SN1D  [0402]  141.95 85.9 270 bottom
L24  BLM15PX121SN1D  [0402]  159.95 83.9 90 bottom
L505  BLM15PX121SN1D  [0402]  142.56 72.9 0 bottom
L506  BLM15PX121SN1D  [0402]  144.57 79.61 180 bottom
L515  4.7 uH  [IND-CDRH104R_SUMIDA]  82.47 40.88 90 top
L516  SRR1005-100M  [IND-SRR1005_BOURNS]  49.3 66.3 0 top
L517  SRR1005-150M  [IND-SRR1005_BOURNS]  67.86 37.07 0 top
L518  SRR1005-100M  [IND-SRR1005_BOURNS]  58.36 73.75 180 top
L519  33 uH  [IND2-74404063330_WURTH]  54.93 51.44 270 top
L520  47 uH  [IND-SRN4018_BOURNS]  65.72 84.45 180 top
L521  47 uH  [IND-SRN4018_BOURNS]  71.44 71.75 90 top
L522  47 uH  [IND-SRN4018_BOURNS]  83.22 70.96 90 top
L523  33 uH  [IND2-74404063330_WURTH]  14.92 44.45 180 top
L524  47 uH  [IND-SRN4018_BOURNS]  26.35 64.14 90 top
L525  47 uH  [IND-SRN4018_BOURNS]  30.8 64.14 90 top
L526  47 uH  [IND-SRN4018_BOURNS]  37.15 51.44 270 top
L527  33 uH  [IND2-74404063330_WURTH]  62.55 93.34 180 top
L528  47 uH  [IND-SRN4018_BOURNS]  72.71 113.67 90 top
L529  47 uH  [IND-SRN4018_BOURNS]  78.42 113.67 90 top
L530  47 uH  [IND-SRN4018_BOURNS]  86.04 109.86 0 top
L531  3.3 uH  [IND-SRN6045TA_BOURNS]  166.69 144.78 0 top
NOREF  -  [unnamed]  183.1 146.35 90 top
NOREF#2  -  [#2]  44.27 24.75 0 top
NOREF#3  -  [unnamed]  43.1 146.35 90 top
NOREF#4  -  [#2]  52.12 24.88 0 top
NOREF#5  -  [#2]  0 0 0 top
NOREF#6  -  [unnamed]  43.1 31.35 90 top
NOREF#7  -  [#2]  -20.4 -19.45 0 top
NOREF#8  -  [#2]  0 0 90 top
NOREF#9  -  [#2]  23.31 16.26 0 top
NOREF#10  -  [unnamed]  183.1 31.35 90 top
NOREF#11  -  [#2]  208.2 171.05 0 top
NOREF#12  -  [#2]  261.11 -80.42 0 top
NOREF#13  -  [#2]  0 151.35 0 top
NOREF#14  -  [#2]  10.08 -47.39 0 top
NOREF#15  -  [#2]  29.54 3.01 0 top
NOREF#16  -  [#2]  0 0 0 top
NOREF#17  -  [unnamed]  166.69 28.57 180 top
NOREF#18  -  [#2]  0 151.35 0 top
NOREF#19  -  [#2]  0 151.35 0 top
NOREF#20  -  [#2]  0 0 90 top
NOREF#21  -  [#2]  -20.4 171.05 0 top
NOREF#22  -  [#2]  0 151.35 0 top
NOREF#23  -  [#2]  31.97 15.43 0 top
NOREF#24  -  [#2]  0 0 90 top
Q1  MMBT2222A  [SOT23]  178.75 21.59 0 bottom
Q6  CSD13383F4  [3-PICOSTAR_3-XFDFN]  168.61 51.75 90 top
Q10  NTD14N03RT4G  [DPAK-A]  80.56 49.77 270 top
Q11  NTD14N03RT4G_CUS  [DPAK-A]  81.2 60.56 270 top
Q12  NDT456P  [SOT223-A]  55.16 126.6 180 top
Q13  ZVN4106FTA  [SOT23-3_DIO-MOD]  57.47 137.79 180 bottom
R1  10k  [0402]  73.34 148.59 0 top
R2  10k  [0402]  73.34 143.51 0 top
R4  27.4  [0402]  81.76 140.97 90 top
R5  27.4  [0402]  82.71 140.97 90 top
R8  0  [0402]  88.91 128.39 0 top
R9  10k  [0402]  120.33 134.62 0 top
R10  100  [0402]  120.33 133.03 0 top
R11  31.6k  [0402]  89.96 126.89 270 top
R13  0  [0402]  87.96 119.39 180 top
R14  0  [0402]  89.96 119.39 0 top
R18  30.1  [0402]  141.92 106.68 270 top
R19  0  [0402]  143.19 106.68 270 top
R20  100k  [0402]  144.46 106.68 270 top
R21  100k  [0402]  145.73 106.68 90 bottom
R22  100k  [0402]  147 106.68 270 top
R29  1M  [0402]  167.96 91.76 90 top
R30  0  [0402]  169.86 92.39 180 top
R31  0  [0402]  169.86 91.12 180 top
R32  200  [0402]  181.29 91.12 180 top
R34  100k  [0402]  160.34 107.95 90 top
R36  100k  [0402]  161.61 105.41 90 bottom
R37  200  [0402]  99.69 38.42 180 top
R38  100k  [0402]  126.05 87.63 180 top
R39  100k  [0402]  126.05 86.36 180 top
R40  681  [0402]  181.29 88.27 180 top
R42  200  [0402]  99.69 34.29 180 top
R43  681  [0402]  99.69 30.16 180 top
R51  0  [0402]  178.12 25.4 270 top
R52  0  [0402]  172.4 25.4 90 top
R53  0  [0402]  182.56 24.13 0 bottom
R54  4.02k  [0603]  178.75 17.78 90 bottom
R55  10k  [0402]  172.4 19.05 270 bottom
R56  0  [0402]  182.56 22.86 0 bottom
R57  0  [0402]  182.56 21.59 0 bottom
R61  330k  [0402]  163.77 55.37 270 top
R62  24k  [0201]  163.85 53.66 270 top
R63  15k  [0402]  165.44 54.93 0 top
R64  22k  [0402]  165.44 53.97 180 top
R65  10  [1210]  168.61 55.25 90 top
R66  10  [1210]  172.08 55.25 90 top
R73  10k  [0402]  150.81 46.99 0 top
R75  100k  [0402]  161.63 50.48 90 top
R76  1k  [0402]  168.61 50.8 180 top
R77  30.1  [0402]  168.61 49.53 0 top
R78  3.3k  [0402]  171.13 46.67 0 top
R79  3.3k  [0402]  173.67 46.67 180 top
R80  0  [0805]  140.34 42.86 270 top
R81  1k  [0402]  150.81 40 180 top
R82  3.3k  [0402]  171.13 42.86 180 top
R83  3.3k  [0402]  173.67 42.86 0 top
R84  10k  [0402]  142.88 143.19 90 bottom
R85  10k  [0402]  161.61 139.7 270 bottom
R86  10k  [0402]  161.61 137.48 90 bottom
R87  10k  [0402]  75.25 136.53 90 bottom
R88  10k  [0402]  58.74 142.24 270 top
R89  10k  [0402]  141.92 132.72 270 bottom
R90  10k  [0402]  132.45 126.39 0 bottom
R91  10k  [0402]  86.96 127.39 0 bottom
R92  10k  [0402]  161.61 121.6 270 bottom
R93  10k  [0402]  142.88 125.09 90 bottom
R94  10k  [0402]  141.92 123.83 90 bottom
R95  10k  [0402]  132.45 124.89 0 bottom
R96  10k  [0402]  132.45 123.39 0 bottom
R97  10k  [0402]  132.45 121.89 0 bottom
R98  10k  [0402]  161.61 119.38 90 bottom
R99  10k  [0402]  132.45 120.39 0 bottom
R100  10k  [0402]  132.45 118.89 0 bottom
R101  10k  [0402]  132.45 117.39 0 bottom
R102  10k  [0402]  141.92 114.62 270 bottom
R103  10k  [0402]  132.45 115.89 0 bottom
R104  0  [0402]  144.46 106.68 270 bottom
R105  100k  [0402]  143.19 106.68 270 bottom
R106  100k  [0402]  141.92 106.68 270 bottom
R108  22.1k  [0603]  170.5 128.91 270 bottom
R109  30.1  [0402]  160.95 102.9 270 bottom
R110  30.1  [0402]  159.95 101.9 270 bottom
R111  30.1  [0402]  157.95 101.9 270 bottom
R112  33.2  [0402]  151.45 103.19 270 bottom
R113  10k  [0402]  144.52 103.34 270 bottom
R114  174  [0402]  137.79 99.38 0 bottom
R116  1M  [0402]  136.45 89.4 0 bottom
R117  0  [0402]  134.3 89.22 0 bottom
R118  0  [0402]  134.3 87.95 0 bottom
R119  1k  [0402]  171.45 84.77 0 bottom
R120  1k  [0402]  167.94 84.9 0 bottom
R121  10k  [0402]  91.44 27.62 90 bottom
R122  100k  [0402]  180.02 85.72 270 bottom
R123  100k  [0402]  177.48 85.72 90 bottom
R124  0  [0402]  155.62 72.48 90 bottom
R125  10k  [0402]  85.09 27.94 90 bottom
R127  0  [0402]  156.53 73.34 90 bottom
R128  10k  [0402]  154.63 72.45 270 bottom
R133  0.47  [0402]  151.13 45.09 90 bottom
R134  0  [0402]  149.22 49.53 90 bottom
R135  0  [0402]  148.27 49.53 90 bottom
R136  0  [0402]  146.37 49.53 90 bottom
R137  0  [0402]  145.41 49.53 90 bottom
R138  0  [0402]  145.41 45.09 0 bottom
R139  3.3k  [0402]  111.44 40.32 270 bottom
R140  3.3k  [0402]  110.17 40.32 270 bottom
R141  10k  [0402]  173.67 44.45 0 bottom
R142  3.3k  [0402]  183.99 39.37 90 bottom
R143  3.3k  [0402]  183.99 37.15 270 bottom
R144  0.47  [0402]  151.13 42.23 270 bottom
R145  0  [0402]  145.41 42.55 0 bottom
R146  3.3k  [0402]  111.44 33.34 270 bottom
R147  3.3k  [0402]  110.17 33.34 270 bottom
R148  100k  [0402]  146.69 38.1 90 bottom
R149  100k  [0402]  145.41 38.1 90 bottom
R150  100k  [0402]  144.15 38.1 90 bottom
R151  100k  [0402]  142.88 38.1 90 bottom
R152  220  [0603]  10.48 125.09 0 top
R153  10k  [0402]  90.49 31.75 180 top
R154  0  [0402]  44.13 76.83 0 top
R155  10k  [0402]  32.7 85.72 180 bottom
R156  1k  [0402]  115.89 76.83 0 top
R157  1k  [0402]  113.45 88.29 0 bottom
R168  0  [0402]  140.02 106.68 90 top
R169  0  [0402]  138.11 106.68 270 bottom
R175  0  [0603]  62.85 66.93 180 top
R176  0  [0603]  66.34 66.28 180 bottom
R179  0.01  [0805WIDE-KRL2012E_SUSUMU]  50.08 79.61 0 top
R181  0  [0603]  50.08 73.9 90 top
R184  0  [0603]  59.34 66.9 180 top
R193  10 K  [0603]  89.22 97.79 180 bottom
R195  10 K  [0603]  89.22 93.34 180 bottom
R196  10 K  [0603]  86.68 90.8 90 bottom
R197  10 K  [0603]  86.04 95.89 270 bottom
R198  10 K  [0603]  67.63 123.19 270 bottom
R200  100k  [0402]  78.42 10.16 0 top
R201  100k  [0402]  49.85 12.7 270 top
R209  100k  [0402]  154.31 114.62 90 bottom
R210  4.99k  [0402]  166.05 111.12 0 bottom
R211  0  [0402]  25.72 84.45 90 bottom
R212  0  [0402]  34.61 79.38 270 bottom
R217  0  [0402]  40.7 84.45 180 bottom
R218  220  [0603]  39.69 88.27 180 bottom
R219  0  [0402]  29.53 85.72 180 bottom
R222  30.1  [0402]  26.03 73.03 270 bottom
R226  220  [0603]  39.69 92.08 180 bottom
R234  0  [0402]  155.88 68.54 90 top
R235  0  [0402]  157.4 69.45 90 top
R237  0  [0402]  158.11 69.99 180 bottom
R246  0  [0805]  167.96 128.27 270 top
R256  10k  [0402]  165.42 94.61 90 bottom
R257  33.2  [0402]  111.44 88.27 90 bottom
R258  33.2  [0402]  103.19 88.27 0 bottom
R259  75  [0402]  146.5 56.85 180 top
R260  0  [0402]  151.05 74.68 180 bottom
R261  0  [0402]  151.96 75.88 180 bottom
R504  10k  [0402]  82.87 17.78 270 bottom
R505  10k  [0402]  80.33 17.78 270 bottom
R506  10k  [0402]  77.79 16.51 270 bottom
R507  0  [0402]  76.52 18.41 0 bottom
R508  10k  [0402]  72.71 17.78 270 bottom
R511  10k  [0402]  125.41 73.03 0 bottom
R517  3.3k  [0402]  75.25 16.51 270 bottom
R519  10k  [0402]  70.17 17.78 270 bottom
R520  1k  [0402]  72.71 14.61 90 bottom
R522  1k  [0402]  67.63 17.78 270 bottom
R523  10k  [0402]  70.17 13.34 90 bottom
R524  1k  [0402]  173.04 27.94 90 top
R525  1k  [0402]  180.66 27.94 180 top
R526  10k  [0402]  174.94 27.94 270 top
R528  0  [0402]  182.56 20.32 0 bottom
R529  6.49k  [0402]  171.13 19.05 270 bottom
R533  0  [0402]  63.82 11.43 90 top
R534  0  [0402]  62.55 11.43 90 top
R535  0  [0402]  61.28 11.43 90 top
R536  0  [0402]  60.01 11.43 90 top
R537  0  [0402]  58.74 11.43 90 top
R538  0  [0402]  57.47 11.43 90 top
R539  0  [0402]  56.2 11.43 90 top
R540  0  [0402]  53.66 11.43 90 top
R542  100k  [0402]  47.94 20.32 90 top
R543  100k  [0402]  50.48 20.32 90 top
R544  100k  [0402]  65.72 11.43 90 top
R545  100k  [0402]  54.93 11.43 270 top
R546  0  [0402]  75.88 10.79 0 top
R547  0  [0402]  66.99 11.43 90 top
R548  0  [0402]  47.94 12.7 90 top
R549  4.99k  [0402]  143.17 65.41 270 top
R550  0  [0402]  45.4 12.7 90 top
R581  10k  [0402]  126.05 10.79 270 bottom
R585  0  [0402]  16.83 108.59 270 bottom
R586  10k  [0402]  17.06 105.01 270 top
R589  30.1  [0402]  134.3 91.44 0 bottom
R590  10k  [0402]  122.24 9.52 0 bottom
R592  47k  [0402]  43.73 113.27 0 bottom
R593  10k  [0402]  42.86 120.65 90 bottom
R594  10k  [0402]  37.78 120.02 90 bottom
R595  10k  [0402]  33.97 121.92 90 bottom
R596  1k  [0402]  9.84 113.03 0 top
R597  1k  [0402]  9.84 115.57 0 top
R598  1k  [0402]  9.84 118.11 0 top
R599  0  [0402]  8.57 108.59 270 bottom
R601  0  [0402]  150.81 113.03 90 bottom
R604  30.1  [0402]  134.3 92.71 0 bottom
R605  10k  [0402]  35.24 81.92 180 bottom
R606  0  [0402]  43.1 102.47 0 top
R607  0  [0402]  43.1 100.57 0 top
R608  0  [0402]  22.54 113.67 180 bottom
R609  1k  [0402]  9.84 114.3 0 top
R610  1k  [0402]  9.84 116.84 0 top
R611  1k  [0402]  9.84 119.38 0 top
R612  33.2  [0402]  5.4 118.75 180 bottom
R613  0  [0402]  147.64 113.03 90 bottom
R614  0  [0402]  140.65 110.49 270 top
R615  0  [0402]  140.02 106.68 270 bottom
R623  10k  [0402]  40.32 81.92 0 top
R626  22  [0402]  141.32 65.46 270 top
R627  0  [0402]  158.43 13.34 270 top
R628  10k  [0402]  13.02 140.97 180 bottom
R629  10k  [0402]  13.02 135.89 180 bottom
R632  10k  [0402]  133.67 55.88 180 bottom
R635  30.1  [0402]  159.07 107.95 90 top
R640  10k  [0402]  133.67 60.96 180 bottom
R642  10k  [0402]  131.13 64.45 270 bottom
R643  10k  [0402]  161.61 69.85 270 top
R644  10k  [0402]  163.14 71.64 0 top
R645  10k  [0402]  132.72 64.45 270 bottom
R646  10k  [0402]  108.9 69.85 0 bottom
R647  10k  [0402]  13.02 33.66 0 bottom
R648  10k  [0402]  13.02 32.38 180 bottom
R649  10k  [0402]  13.02 31.11 180 bottom
R650  0  [0402]  7.94 33.66 270 bottom
R651  0  [0402]  132.4 38.73 90 bottom
R652  0  [0402]  131.13 34.92 270 bottom
R653  0  [0402]  129.22 34.92 270 bottom
R654  0  [0402]  127.32 34.92 270 bottom
R655  30.1  [0402]  169.86 92.08 180 bottom
R656  30.1  [0402]  169.86 90.8 180 bottom
R660  10k  [0402]  110.49 68.26 270 bottom
R661  10k  [0402]  117.16 74.61 0 bottom
R662  10k  [0402]  112.08 68.26 270 bottom
R663  10k  [0402]  113.35 68.26 270 bottom
R664  10k  [0402]  114.62 68.26 270 bottom
R665  10k  [0402]  115.57 68.26 270 bottom
R666  10k  [0402]  118.43 68.26 270 bottom
R667  10k  [0402]  107.63 73.34 0 bottom
R668  0  [0402]  8.25 26.67 90 bottom
R669  30.1  [0402]  181.93 89.53 0 bottom
R670  0  [0402]  181.29 72.39 270 bottom
R671  0  [0402]  177.59 72.55 180 bottom
R672  30.1  [0402]  164.15 106.68 270 bottom
R673  30.1  [0402]  164.15 107.95 270 top
R674  0  [0402]  159.15 69.71 90 top
R675  0  [0402]  155.95 71.33 90 top
R676  0  [0402]  141.92 110.49 270 top
R677  0  [0402]  147.64 115.57 270 bottom
R678  0  [0402]  150.81 115.57 270 bottom
R679  0  [0402]  143.83 110.49 270 top
R680  0  [0402]  154.31 110.49 270 bottom
R706  0  [0402]  173.04 93.98 180 bottom
R710  0  [0402]  171.13 69.22 180 bottom
R711  0  [0402]  171.13 71.12 180 bottom
R712  10k  [0402]  150.18 62.86 270 top
R713  10k  [0402]  153.23 74.46 270 bottom
R714  100k  [0402]  169.86 114.3 270 top
R715  100k  [0402]  171.77 114.3 270 top
R716  100k  [0402]  167.96 114.3 270 top
R717  100k  [0402]  166.05 114.3 270 top
R739  0.1  [0805]  80.18 56.85 0 bottom
R740  0.01  [0805WIDE-KRL2012E_SUSUMU]  90.72 40.88 90 top
R742  2.18k  [0603]  74.85 56.65 90 bottom
R744  0.01  [0805WIDE-KRL2012E_SUSUMU]  83.26 55.46 270 top
R747  1.74 K  [0603]  77.39 59.29 0 bottom
R750  1.74 K  [0603]  75.55 61.09 180 bottom
R751  3.4K  [0603]  72.06 60.82 90 bottom
R752  0  [0603]  77.15 34.29 180 top
R754  0  [0603]  52.86 79.12 90 top
R755  0.01  [0805WIDE-KRL2012E_SUSUMU]  80.96 33.66 270 top
R756  0.01  [0805WIDE-KRL2012E_SUSUMU]  52.86 82.55 0 top
R758  0  [0603]  71.36 44.47 90 top
R759  0  [0603]  63.44 68.47 0 top
R763  3.4K  [0603]  58.1 60.33 0 bottom
R764  3.4K  [0603]  73.96 67.04 270 bottom
R765  3.4K  [0603]  77.39 62.85 180 bottom
R766  3.4K  [0603]  59.37 64.77 0 bottom
R767  3.4K  [0603]  72.18 66.4 270 bottom
R768  0  [0603]  51.63 37.95 90 bottom
R769  0  [0603]  44.01 41.12 270 bottom
R770  0.01  [0805WIDE-KRL2012E_SUSUMU]  60.73 53.96 0 top
R771  0  [0603]  50.99 41.76 270 bottom
R772  33  [0603]  60.01 64.14 180 top
R773  150  [0603]  49.09 40.49 90 bottom
R774  150  [0603]  44.01 37.31 90 bottom
R775  150  [0603]  53.53 37.95 90 bottom
R776  2.2  [0603]  66.36 54.61 0 bottom
R777  10 K  [0603]  56.2 60.96 270 top
R778  0.1  [0805]  36.75 50.4 0 bottom
R779  0  [0603]  32.7 48.26 270 bottom
R780  0  [0603]  28.89 59.69 90 bottom
R781  0  [0603]  33.34 43.83 90 top
R782  0  [0603]  26.99 59.69 90 bottom
R783  3.4K  [0603]  18.73 53.97 0 bottom
R784  0  [0603]  18.73 55.88 0 bottom
R785  0  [0603]  23.81 45.09 270 bottom
R786  0  [0603]  35.88 55.88 0 bottom
R787  0  [0603]  25.08 40.64 270 bottom
R788  0  [0603]  36.51 52.7 0 bottom
R789  33  [0603]  18.73 57.78 180 bottom
R790  0  [0603]  23.81 55.88 180 bottom
R791  0.01  [0805WIDE-KRL2012E_SUSUMU]  20.64 46.99 0 top
R792  0  [0603]  28.89 41.27 270 bottom
R793  0  [0603]  33.34 59.05 90 bottom
R794  150  [0603]  32.07 41.27 180 bottom
R795  150  [0603]  24.68 37.07 90 bottom
R796  150  [0603]  27.62 36.83 180 bottom
R797  2.2  [0603]  24.68 48.5 180 bottom
R798  10 K  [0603]  16.83 51.44 270 bottom
R799  0.1  [0805]  84.88 101.13 0 bottom
R800  0  [0603]  85.62 98.99 0 top
R801  0  [0603]  78.02 108.82 90 bottom
R802  0  [0603]  83.21 94.07 180 top
R803  0  [0603]  68.3 105.34 180 top
R804  3.4K  [0603]  69.53 104.78 270 bottom
R805  0  [0603]  66.36 102.87 0 bottom
R806  0  [0603]  71.44 93.98 270 bottom
R807  0  [0603]  85.41 102.87 0 top
R808  0  [0603]  75.88 92.08 270 bottom
R809  0  [0603]  85.41 100.97 0 top
R810  33  [0603]  71.44 104.78 90 bottom
R811  0  [0603]  73.34 109.22 90 bottom
R812  0.01  [0805WIDE-KRL2012E_SUSUMU]  68.26 96.52 0 top
R813  0  [0603]  79.06 92.08 270 bottom
R814  0  [0603]  84.77 104.14 0 bottom
R815  150  [0603]  79.69 85.09 0 bottom
R816  150  [0603]  70.8 83.82 90 bottom
R817  150  [0603]  79.06 88.27 90 bottom
R818  2.2  [0603]  75.25 96.52 0 bottom
R819  10 K  [0603]  54.93 95.89 0 bottom
R820  1 Meg  [0805]  63.18 122.56 0 top
R821  10 K  [0603]  79.69 143.51 90 bottom
R822  100K  [0603]  54.93 133.35 0 top
R823  10 K  [0603]  48.58 138.43 0 top
R824  100K  [0603]  48.58 140.97 0 top
R825  20K  [0603]  59.37 133.35 0 top
R826  15K  [0603]  60.01 134.62 90 bottom
R827  150k  [0603]  60.24 121.52 270 top
R828  130K  [0603]  60.64 129.54 270 bottom
R829  1 K  [0603]  48.58 140.97 180 bottom
R830  0  [0603]  53.02 140.97 180 top
R831  12  [0805]  83.5 87 180 bottom
R832  10 K  [0603]  90.49 99.7 0 top
R833  10 K  [0603]  171.13 133.35 180 bottom
R834  0.01  [0805WIDE-KRL2012E_SUSUMU]  167.96 137.79 0 top
R835  12  [0805]  96.2 95.25 270 bottom
R836  73.2k  [0603]  165.86 131.94 0 bottom
R837  12  [0805]  95.57 90.17 180 bottom
R838  143 K  [0402]  58.97 125.33 180 bottom
R839  100K  [0603]  90.49 109.22 270 bottom
R840  0  [0603]  48.18 59.93 180 top
R841  0  [0603]  47.94 57.78 0 top
R842  0  [0603]  47.94 55.88 0 top
R843  10 K  [0603]  42.23 51.44 180 top
R844  0  [0603]  42.46 58.66 180 top
R845  0  [0603]  42.23 56.52 180 top
R846  0  [0603]  42.23 53.97 180 top
R847  0  [0603]  47.94 53.97 180 top
R848  0  [0603]  47.94 51.44 180 top
R849  0  [0603]  47.94 48.89 180 top
R850  0  [0603]  47.94 46.35 180 top
R851  0  [0603]  16.19 53.97 180 top
R852  0  [0603]  54.93 91.44 180 top
R853  1k  [0402]  42.23 128.27 180 bottom
R854  1k  [0402]  39.05 128.27 180 bottom
R855  1k  [0402]  33.34 126.37 180 bottom
R856  200  [0402]  21.91 115.57 180 bottom
R857  220  [0603]  10.48 121.28 0 top
R858  220  [0603]  10.48 123.19 0 top
R859  10k  [0402]  140.02 57.15 270 bottom
R860  10k  [0402]  96.84 65.41 180 bottom
R861  10k  [0402]  10.48 96.14 180 top
R862  10k  [0402]  9.84 97.79 270 top
R863  0  [0402]  11.75 97.16 0 top
R864  0  [0402]  11.11 92.08 180 top
R865  10k  [0402]  60.01 142.24 270 top
R866  0  [0402]  145.73 110.49 270 top
R867  0  [0402]  148.27 110.49 270 top
R868  0  [0402]  150.81 110.49 270 top
R869  4.99k  [0402]  157.16 113.67 180 bottom
R870  0  [0402]  147 106.68 270 bottom
R871  0  [0402]  145.73 106.68 90 top
R872  100K  [0603]  127.95 122.56 0 top
R873  110  [0603]  137.48 137.16 270 bottom
R874  20 K  [0603]  126.05 129.54 270 bottom
R875  2.2 K  [0603]  122.24 123.83 90 bottom
R876  100K  [0603]  96.2 126.37 270 bottom
R877  110  [0603]  93.66 119.38 90 bottom
R878  10 K  [0603]  98.11 126.37 270 bottom
R879  2.2 K  [0603]  103.82 120.65 90 bottom
R880  100K  [0603]  133.67 105.41 270 top
R881  110  [0603]  127.95 111.12 0 bottom
R882  10 K  [0603]  130.49 107.31 0 top
R883  2.2 K  [0603]  130.49 107.31 180 bottom
R884  3.3k  [0402]  166.69 36.2 270 bottom
R885  3.3k  [0402]  165.42 36.2 270 bottom
R886  0  [0402]  86.51 94.55 180 top
R887  0  [0402]  80.26 90.56 90 top
SW1  -  [GT11MSCBE]  67.31 146.05 180 top
SW3  -  [GT11MSCBE]  9.84 138.43 180 top
SW5  GT12MSCBE  [SW5_GT12MSCBE]  52.39 146.05 180 top
TP1  TP_BLK  [TP_KEYSTONE_5011]  156.53 147.95 0 top
TP2  TP_BLK  [TP_KEYSTONE_5011]  102.55 131.44 0 top
TP3  TP,28mil Drill,48mil Pad  [HTP-48RD28]  118.43 138.75 0 top
TP5  TP,28mil Drill,48mil Pad  [HTP-48RD28]  120.65 138.75 0 top
TP6  TP,28mil Drill,48mil Pad  [HTP-48RD28]  122.87 138.75 0 top
TP7  TP,20mil PAD  [20MIL_PAD]  123.82 140.97 0 top
TP8  TP,20mil PAD  [20MIL_PAD]  164.15 139.7 0 top
TP9  TP,28mil Drill,48mil Pad  [HTP-48RD28]  83.96 132.39 90 top
TP11  TP_BLK  [TP_KEYSTONE_5011]  17.46 133.98 0 top
TP12  TP,20mil PAD  [20MIL_PAD]  164.15 121.6 0 top
TP14  TP_BLK  [TP_KEYSTONE_5011]  35.24 24.77 0 top
TP20  TP_WHT  [TP_KEYSTONE_5011]  177.48 9.52 0 top
TP21  TP,28mil Drill,48mil Pad  [HTP-48RD28]  162.73 108.44 0 top
TP22  TP,20mil PAD  [20MIL_PAD]  127.63 87.63 0 top
TP23  TP,20mil PAD  [20MIL_PAD]  127.63 86.36 0 top
TP24  TP,28mil Drill,48mil Pad  [HTP-48RD28]  177.8 82.87 0 top
TP32  TP,20mil PAD  [20MIL_PAD]  12.38 126.37 0 top
TP33  TP,20mil PAD  [20MIL_PAD]  14.29 126.37 0 top
TP34  TP,20mil PAD  [20MIL_PAD]  16.19 126.37 0 top
TP35  TP,20mil PAD  [20MIL_PAD]  18.1 126.37 0 top
TP36  TP,20mil PAD  [20MIL_PAD]  20 127 0 top
TP37  TP,20mil PAD  [20MIL_PAD]  21.91 127 0 top
TP38  TP_BLK  [TP_KEYSTONE_5011]  6.67 60.33 0 top
TP39  TP_BLK  [TP_KEYSTONE_5011]  178.35 38.97 0 top
TP40  TP,28mil Drill,48mil Pad  [HTP-48RD28]  81.6 10.79 0 top
TP41  TP,20mil PAD  [20MIL_PAD]  30.16 127 90 top
TP42  TP,20mil PAD  [20MIL_PAD]  32.07 126.37 90 top
TP43  TP,20mil PAD  [20MIL_PAD]  33.97 126.37 90 top
TP46  TP,28mil Drill,48mil Pad  [HTP-48RD28]  6.67 110.49 0 top
TP47  TP,28mil Drill,48mil Pad  [HTP-48RD28]  156.1 15.25 0 top
TP48  TP,28mil Drill,48mil Pad  [HTP-48RD28]  117.16 10.79 0 top
TP49  TP,28mil Drill,48mil Pad  [HTP-48RD28]  114.62 10.79 0 top
TP50  TP,28mil Drill,48mil Pad  [HTP-48RD28]  112.71 10.79 0 top
TP51  TP,28mil Drill,48mil Pad  [HTP-48RD28]  110.81 10.79 0 top
TP52  TP,28mil Drill,48mil Pad  [HTP-48RD28]  108.9 10.79 0 top
TP53  TP,28mil Drill,48mil Pad  [HTP-48RD28]  107 10.79 0 top
TP54  TP,28mil Drill,48mil Pad  [HTP-48RD28]  92.39 10.79 0 top
TP55  TP,28mil Drill,48mil Pad  [HTP-48RD28]  88.58 10.79 0 top
TP56  TP,28mil Drill,48mil Pad  [HTP-48RD28]  85.41 10.79 0 top
TP64  TP,20mil PAD  [20MIL_PAD]  14.92 122.56 90 top
TP65  TP,20mil PAD  [20MIL_PAD]  14.92 118.75 90 top
TP66  TP,20mil PAD  [20MIL_PAD]  14.92 120.65 90 top
TP67  TP,20mil PAD  [20MIL_PAD]  14.92 116.84 90 top
TP68  TP,20mil PAD  [20MIL_PAD]  14.92 113.03 90 top
TP69  TP,20mil PAD  [20MIL_PAD]  39.69 120.02 90 top
TP70  TP,20mil PAD  [20MIL_PAD]  39.69 116.2 90 top
TP71  TP,20mil PAD  [20MIL_PAD]  39.69 111.12 90 top
TP72  TP,20mil PAD  [20MIL_PAD]  38.42 104.78 90 top
TP73  TP,20mil PAD  [20MIL_PAD]  39.69 118.11 90 top
TP74  TP,20mil PAD  [20MIL_PAD]  39.69 114.3 0 top
TP75  TP,20mil PAD  [20MIL_PAD]  39.69 109.22 90 top
TP76  TP,20mil PAD  [20MIL_PAD]  40.32 105.41 90 top
TP77  TP,40mil Drill,60mil Pad  [TP-60RD40]  39.05 107.31 90 top
TP78  TP,20mil PAD  [20MIL_PAD]  135.81 13.57 270 top
TP79  TP,20mil PAD  [20MIL_PAD]  140.02 13.34 270 top
TP80  TP,20mil PAD  [20MIL_PAD]  143.83 13.34 270 top
TP81  TP,20mil PAD  [20MIL_PAD]  133.9 13.57 270 top
TP82  TP,20mil PAD  [20MIL_PAD]  138.11 13.34 270 top
TP83  TP,20mil PAD  [20MIL_PAD]  141.92 13.34 270 top
TP84  TP,20mil PAD  [20MIL_PAD]  132.63 14.84 270 top
TP85  TP,20mil PAD  [20MIL_PAD]  138.11 15.24 270 top
TP86  TP,20mil PAD  [20MIL_PAD]  141.92 15.24 270 top
TP87  TP,20mil PAD  [20MIL_PAD]  130.73 14.84 270 top
TP88  TP,20mil PAD  [20MIL_PAD]  136.21 15.24 270 top
TP89  TP,20mil PAD  [20MIL_PAD]  140.02 15.24 270 top
TP106  TP,28mil Drill,48mil Pad  [HTP-48RD28]  120.97 88.27 0 top
TP107  TP,28mil Drill,48mil Pad  [HTP-48RD28]  115.25 94.61 0 top
TP108  TP,28mil Drill,48mil Pad  [HTP-48RD28]  112.08 97.16 0 top
TP109  TP,28mil Drill,48mil Pad  [HTP-48RD28]  124.78 105.41 0 top
TP111  TP,20mil PAD  [20MIL_PAD]  16.83 109.86 270 top
TP112  TP,20mil PAD  [20MIL_PAD]  14.92 114.94 270 top
TP113  TP,20mil PAD  [20MIL_PAD]  19.37 104.78 270 top
TP114  TP,20mil PAD  [20MIL_PAD]  20.64 102.87 270 top
TP115  TP,20mil PAD  [20MIL_PAD]  21.27 104.78 270 top
TP116  TP,20mil PAD  [20MIL_PAD]  22.54 102.87 270 top
TP117  TP,20mil PAD  [20MIL_PAD]  23.18 104.78 270 top
TP118  TP,20mil PAD  [20MIL_PAD]  24.45 102.87 270 top
TP119  TP,20mil PAD  [20MIL_PAD]  25.08 104.78 270 top
TP120  TP,20mil PAD  [20MIL_PAD]  26.35 102.87 270 top
TP121  TP,20mil PAD  [20MIL_PAD]  26.99 104.78 270 top
TP122  TP,20mil PAD  [20MIL_PAD]  28.26 102.87 270 top
TP123  TP,20mil PAD  [20MIL_PAD]  28.89 104.78 270 top
TP124  TP,20mil PAD  [20MIL_PAD]  30.16 102.87 270 top
TP125  TP,20mil PAD  [20MIL_PAD]  30.8 104.78 90 top
TP126  TP,20mil PAD  [20MIL_PAD]  32.07 102.87 90 top
TP127  TP,20mil PAD  [20MIL_PAD]  39.05 102.23 90 top
TP128  TP,20mil PAD  [20MIL_PAD]  40.32 103.51 90 top
TP129  TP_WHT  [TP_KEYSTONE_5011]  44.77 80.01 0 top
TP130  TP,20mil PAD  [20MIL_PAD]  147.64 13.34 0 top
TP131  TP,20mil PAD  [20MIL_PAD]  151.45 13.34 0 top
TP132  TP,20mil PAD  [20MIL_PAD]  155.26 13.34 0 top
TP133  TP,20mil PAD  [20MIL_PAD]  145.73 13.34 270 top
TP134  TP,20mil PAD  [20MIL_PAD]  149.54 13.34 270 top
TP135  TP,20mil PAD  [20MIL_PAD]  153.35 13.34 270 top
TP136  TP,20mil PAD  [20MIL_PAD]  145.73 15.24 270 top
TP137  TP,20mil PAD  [20MIL_PAD]  149.54 15.24 270 top
TP138  TP,20mil PAD  [20MIL_PAD]  153.35 15.24 270 top
TP139  TP,20mil PAD  [20MIL_PAD]  143.83 15.24 270 top
TP140  TP,20mil PAD  [20MIL_PAD]  147.64 15.24 270 top
TP141  TP,20mil PAD  [20MIL_PAD]  151.45 15.24 270 top
TP144  TP_WHT  [TP_KEYSTONE_5011]  18.1 88.27 270 top
TP145  TP_WHT  [TP_KEYSTONE_5011]  18.1 84.45 270 top
TP146  TP_WHT  [TP_KEYSTONE_5011]  22.54 84.45 0 top
TP147  TP_WHT  [TP_KEYSTONE_5011]  13.65 88.27 270 top
TP148  TP_WHT  [TP_KEYSTONE_5011]  111.44 48.89 0 top
TP149  TP_WHT  [TP_KEYSTONE_5011]  122.24 65.41 0 top
